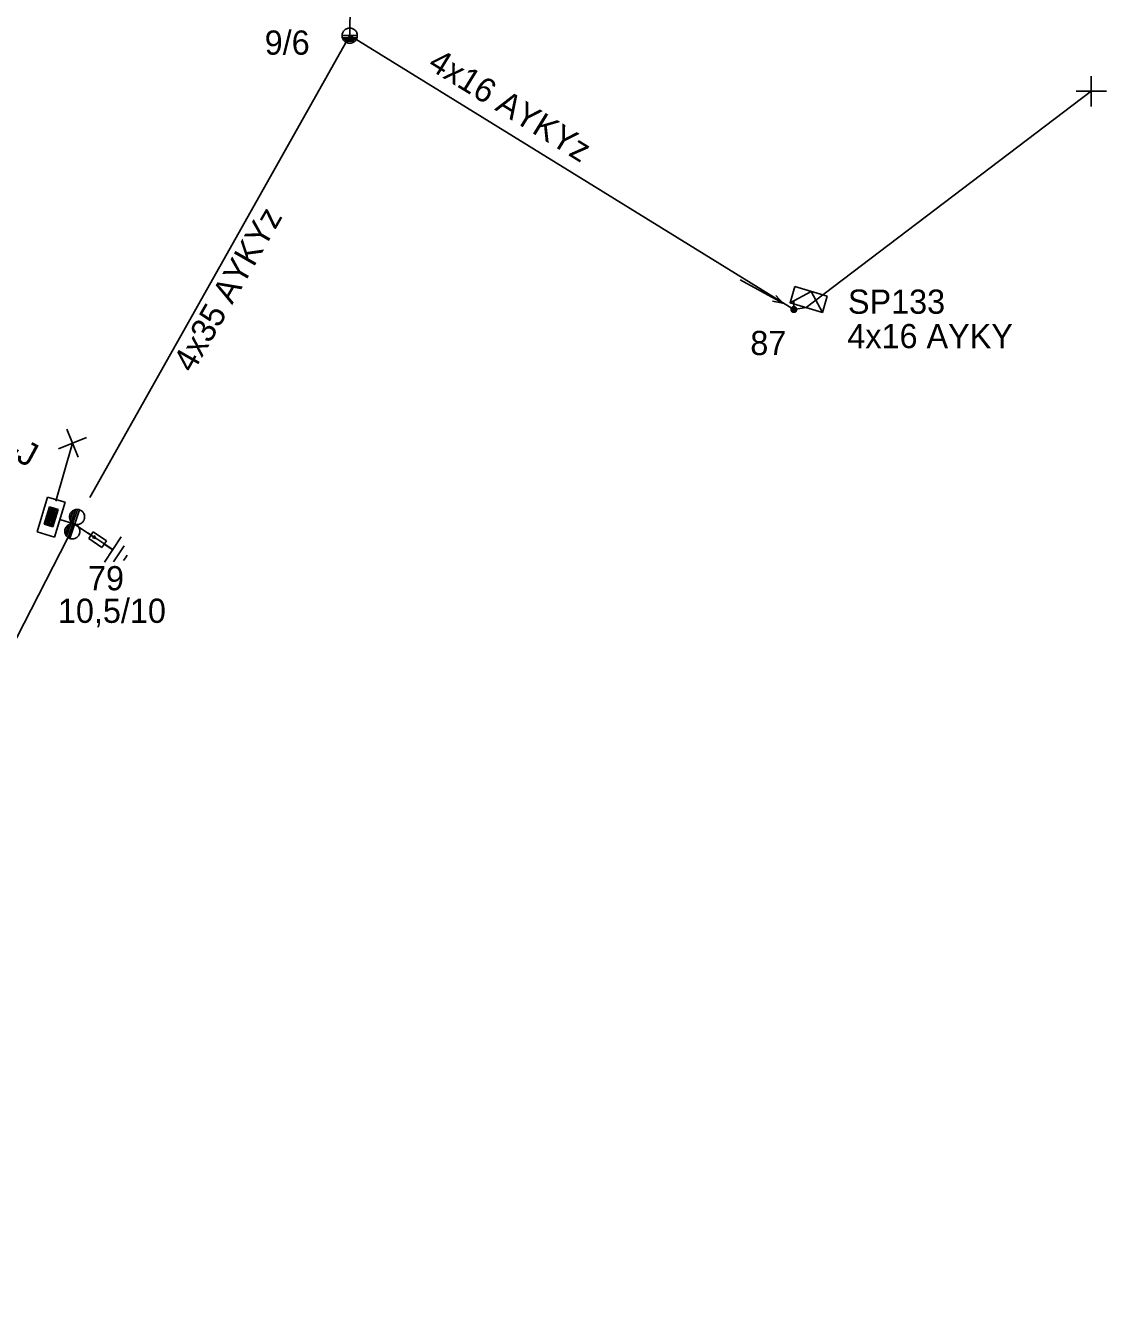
# Model space of a CAD drawing. Extents: x -788458 to -786145, y -1154772 to -1152372.
# Drawn here: x -787177.6 to -787132.9, y -1152514.5 to -1152461.7 of the extents above; entities that cross this region are included whole.
import ezdxf

# ---------------------------------------------------------------- set-up
doc = ezdxf.new("R2010")
doc.units = 0
for name, color, linetype in [('Vrstva 1', 7, 'Continuous'), ('Vrstva 12', 7, 'Continuous'), ('Vrstva 13', 7, 'Continuous'), ('Vrstva 14', 7, 'Continuous'), ('Vrstva 15', 7, 'Continuous'), ('Vrstva 16', 7, 'Continuous'), ('Vrstva 2', 7, 'Continuous'), ('Vrstva 28', 7, 'Continuous'), ('Vrstva 31', 7, 'Continuous'), ('Vrstva 33', 7, 'Continuous'), ('Vrstva 34', 7, 'Continuous'), ('Vrstva 5', 7, 'Continuous'), ('Vrstva 52', 7, 'Continuous'), ('Vrstva 53', 7, 'Continuous'), ('Vrstva 54', 7, 'Continuous'), ('Vrstva 59', 7, 'Continuous'), ('Vrstva 6', 7, 'Continuous'), ('Vrstva 8', 7, 'Continuous'), ('Vrstva 9', 7, 'Continuous')]:
    doc.layers.add(name, color=color, linetype=linetype)

# ---------------------------------------------------------------- blocks, each defined once
blk = doc.blocks.new('NN440')
at = {"layer": 'Vrstva 2'}
for points in [[(0.63, 0), (0.63, 0.06), (0.62, 0.13), (0.6, 0.19), (0.58, 0.25), (0.55, 0.31), (0.51, 0.37), (0.47, 0.42), (0.42, 0.46), (0.37, 0.51), (0.32, 0.54), (0.26, 0.57), (0.2, 0.59), (0.13, 0.61), (0.07, 0.62), (0, 0.63), (-0.06, 0.62), (-0.13, 0.61), (-0.19, 0.59), (-0.26, 0.57), (-0.31, 0.54), (-0.37, 0.51), (-0.42, 0.46), (-0.47, 0.42), (-0.51, 0.37), (-0.54, 0.31), (-0.57, 0.25), (-0.6, 0.19), (-0.62, 0.13), (-0.63, 0.06), (-0.63, 0), (-0.63, -0.07), (-0.62, -0.14), (-0.6, -0.2), (-0.57, -0.26), (-0.54, -0.32), (-0.51, -0.37), (-0.47, -0.43), (-0.42, -0.47), (-0.37, -0.51), (-0.31, -0.55), (-0.26, -0.58), (-0.19, -0.6), (-0.13, -0.62), (-0.06, -0.63), (0, -0.63), (0.07, -0.63), (0.13, -0.62), (0.2, -0.6), (0.26, -0.58), (0.32, -0.55), (0.37, -0.51), (0.42, -0.47), (0.47, -0.43), (0.51, -0.37), (0.55, -0.32), (0.58, -0.26), (0.6, -0.2), (0.62, -0.14), (0.63, -0.07), (0.63, 0)], [(-0.63, 0), (0.63, 0)], [(-0.6, -0.18), (0.57, -0.18)], [(-0.51, -0.32), (0.5, -0.32)], [(-0.37, -0.47), (0.35, -0.47)]]:
    blk.add_lwpolyline(points, dxfattribs=at)
blk = doc.blocks.new('NN450')
at = {"layer": 'Vrstva 2'}
for points in [[(0, 0), (0, 0.07), (-0.01, 0.13), (-0.03, 0.19), (-0.05, 0.25), (-0.08, 0.31), (-0.12, 0.37), (-0.16, 0.42), (-0.21, 0.46), (-0.26, 0.51), (-0.31, 0.54), (-0.37, 0.57), (-0.43, 0.59), (-0.5, 0.61), (-0.56, 0.62), (-0.63, 0.62), (-0.69, 0.62), (-0.75, 0.61), (-0.82, 0.59), (-0.88, 0.57), (-0.94, 0.54), (-0.99, 0.51), (-1.04, 0.46), (-1.09, 0.42), (-1.13, 0.37), (-1.17, 0.31), (-1.2, 0.25), (-1.22, 0.19), (-1.24, 0.13), (-1.25, 0.07), (-1.25, 0), (-1.25, -0.07), (-1.24, -0.13), (-1.22, -0.19), (-1.2, -0.25), (-1.17, -0.31), (-1.13, -0.37), (-1.09, -0.42), (-1.04, -0.46), (-0.99, -0.51), (-0.94, -0.54), (-0.88, -0.57), (-0.82, -0.59), (-0.75, -0.61), (-0.69, -0.62), (-0.62, -0.63), (-0.56, -0.62), (-0.5, -0.61), (-0.43, -0.59), (-0.37, -0.57), (-0.31, -0.54), (-0.26, -0.51), (-0.21, -0.46), (-0.16, -0.42), (-0.12, -0.37), (-0.08, -0.31), (-0.05, -0.25), (-0.03, -0.19), (-0.01, -0.13), (0, -0.07), (0, 0)], [(1.25, 0), (1.25, 0.07), (1.24, 0.13), (1.22, 0.19), (1.2, 0.25), (1.17, 0.31), (1.13, 0.37), (1.09, 0.42), (1.04, 0.46), (0.99, 0.51), (0.94, 0.54), (0.88, 0.57), (0.82, 0.59), (0.75, 0.61), (0.69, 0.62), (0.62, 0.62), (0.56, 0.62), (0.5, 0.61), (0.43, 0.59), (0.37, 0.57), (0.31, 0.54), (0.26, 0.51), (0.21, 0.46), (0.16, 0.42), (0.12, 0.37), (0.08, 0.31), (0.05, 0.25), (0.03, 0.19), (0.01, 0.13), (0, 0.07), (0, 0), (0, -0.07), (0.01, -0.13), (0.03, -0.19), (0.05, -0.25), (0.08, -0.31), (0.12, -0.37), (0.16, -0.42), (0.21, -0.46), (0.26, -0.51), (0.31, -0.54), (0.37, -0.57), (0.43, -0.59), (0.5, -0.61), (0.56, -0.62), (0.63, -0.63), (0.69, -0.62), (0.75, -0.61), (0.82, -0.59), (0.88, -0.57), (0.94, -0.54), (0.99, -0.51), (1.04, -0.46), (1.09, -0.42), (1.13, -0.37), (1.17, -0.31), (1.2, -0.25), (1.22, -0.19), (1.24, -0.13), (1.25, -0.07), (1.25, 0)], [(-1.25, 0), (1.25, 0)], [(-1.23, -0.16), (-0.02, -0.16)], [(-1.16, -0.32), (-0.09, -0.32)], [(-1.03, -0.47), (-0.22, -0.47)], [(0.02, -0.16), (1.23, -0.16)], [(0.09, -0.32), (1.16, -0.32)], [(0.22, -0.47), (1.03, -0.47)]]:
    blk.add_lwpolyline(points, dxfattribs=at)
blk = doc.blocks.new('NN565')
at = {"layer": 'Vrstva 2'}
for points in [[(0.015, 0.528), (0.015, 2.528)], [(0.157, 0.937), (0.015, 0.528), (-0.119, 0.937)]]:
    blk.add_lwpolyline(points, dxfattribs=at)
blk = doc.blocks.new('NN800')
at = {"layer": 'Vrstva 1'}
for points in [[(-0.442, 0.442), (0.442, -0.442)], [(-0.442, -0.442), (0.442, 0.442)]]:
    blk.add_lwpolyline(points, dxfattribs=at)
blk = doc.blocks.new('NN820')
at = {"layer": 'Vrstva 13'}
for points in [[(-0.003, 0.004), (-0.003, -1.049)], [(-0.165, -0.813), (0.165, -0.813)], [(-0.165, -1.473), (-0.165, -0.813)], [(-0.003, -1.049), (-0.062, -0.926)], [(-0.003, -1.049), (0.057, -0.926)], [(0.165, -0.813), (0.165, -1.473)], [(0.165, -1.473), (-0.165, -1.473)], [(-0.003, -1.473), (-0.003, -1.871)]]:
    blk.add_lwpolyline(points, dxfattribs=at)
blk = doc.blocks.new('NN620')
at = {"layer": 'Vrstva 8'}
for points in [[(0.752, 0.004), (-0.748, 0.004)], [(-0.748, 0.004), (-0.748, -0.746)], [(0.752, -0.746), (0.752, 0.004)], [(0.368, -0.18), (-0.376, -0.18)], [(-0.376, -0.18), (-0.376, -0.558)], [(0.321, -0.227), (-0.329, -0.227)], [(-0.329, -0.227), (-0.329, -0.51)], [(-0.329, -0.51), (0.321, -0.51)], [(0.274, -0.274), (-0.281, -0.274)], [(-0.281, -0.274), (-0.281, -0.463)], [(-0.281, -0.463), (0.274, -0.463)], [(0.227, -0.321), (-0.234, -0.321)], [(-0.234, -0.321), (-0.234, -0.416)], [(-0.234, -0.416), (0.227, -0.416)], [(-0.193, -0.369), (0.185, -0.369)], [(0.227, -0.416), (0.227, -0.321)], [(0.274, -0.463), (0.274, -0.274)], [(0.321, -0.51), (0.321, -0.227)], [(0.368, -0.558), (0.368, -0.18)], [(-0.748, -0.746), (0.752, -0.746)], [(-0.376, -0.558), (0.368, -0.558)]]:
    blk.add_lwpolyline(points, dxfattribs=at)
blk = doc.blocks.new('NN630')
at = {"layer": 'Vrstva 9'}
for points in [[(-0.003, -0.7), (-0.703, 0)], [(-0.703, -0.7), (-0.703, 0), (0.697, 0), (0.697, -0.7)], [(-0.003, -0.7), (0.697, 0)], [(-0.703, -0.7), (0.697, -0.7)]]:
    blk.add_lwpolyline(points, dxfattribs=at)
blk = doc.blocks.new('NN810')
at = {"layer": 'Vrstva 14'}
for points in [[(0.004, -0.64), (0.004, -1.89)], [(0.629, -1.89), (-0.621, -1.89)], [(0.388, -2.2), (-0.399, -2.2)], [(0.004, -2.515), (-0.124, -2.515)], [(0.137, -2.515), (0.004, -2.515)]]:
    blk.add_lwpolyline(points, dxfattribs=at)
blk = doc.blocks.new('NN500')
at = {"layer": 'Vrstva 2'}
for points in [[(0, -0.24), (0.02, -0.23), (0.05, -0.23), (0.07, -0.22), (0.09, -0.22), (0.12, -0.2), (0.14, -0.19), (0.16, -0.18), (0.17, -0.16), (0.19, -0.14), (0.2, -0.12), (0.21, -0.1), (0.22, -0.07), (0.23, -0.05), (0.23, -0.02), (0.23, 0), (0.23, 0.02), (0.23, 0.05), (0.22, 0.07), (0.21, 0.1), (0.2, 0.12), (0.19, 0.14), (0.17, 0.16), (0.16, 0.17), (0.14, 0.19), (0.12, 0.2), (0.09, 0.21), (0.07, 0.22), (0.05, 0.23), (0.02, 0.23), (0, 0.23), (-0.03, 0.23), (-0.05, 0.23), (-0.07, 0.22), (-0.1, 0.21), (-0.12, 0.2), (-0.14, 0.19), (-0.16, 0.17), (-0.18, 0.16), (-0.19, 0.14), (-0.2, 0.12), (-0.22, 0.1), (-0.22, 0.07), (-0.23, 0.05), (-0.23, 0.02), (-0.24, 0), (-0.23, -0.02), (-0.23, -0.05), (-0.22, -0.07), (-0.22, -0.1), (-0.2, -0.12), (-0.19, -0.14), (-0.18, -0.16), (-0.16, -0.18), (-0.14, -0.19), (-0.12, -0.2), (-0.1, -0.22), (-0.07, -0.22), (-0.05, -0.23), (-0.03, -0.23), (0, -0.24)], [(0, -0.24), (0.02, -0.23), (0.05, -0.23), (0.07, -0.22), (0.09, -0.22), (0.12, -0.2), (0.14, -0.19), (0.16, -0.18), (0.17, -0.16), (0.19, -0.14), (0.2, -0.12), (0.21, -0.1), (0.22, -0.07), (0.23, -0.05), (0.23, -0.02), (0.23, 0), (0.23, 0.02), (0.23, 0.05), (0.22, 0.07), (0.21, 0.1), (0.2, 0.12), (0.19, 0.14), (0.17, 0.16), (0.16, 0.17), (0.14, 0.19), (0.12, 0.2), (0.09, 0.21), (0.07, 0.22), (0.05, 0.23), (0.02, 0.23), (0, 0.23), (-0.03, 0.23), (-0.05, 0.23), (-0.07, 0.22), (-0.1, 0.21), (-0.12, 0.2), (-0.14, 0.19), (-0.16, 0.17), (-0.18, 0.16), (-0.19, 0.14), (-0.2, 0.12), (-0.22, 0.1), (-0.22, 0.07), (-0.23, 0.05), (-0.23, 0.02), (-0.24, 0), (-0.23, -0.02), (-0.23, -0.05), (-0.22, -0.07), (-0.22, -0.1), (-0.2, -0.12), (-0.19, -0.14), (-0.18, -0.16), (-0.16, -0.18), (-0.14, -0.19), (-0.12, -0.2), (-0.1, -0.22), (-0.07, -0.22), (-0.05, -0.23), (-0.03, -0.23), (0, -0.24)], [(0, -0.21), (0.02, -0.2), (0.04, -0.2), (0.06, -0.2), (0.08, -0.19), (0.1, -0.18), (0.12, -0.17), (0.14, -0.15), (0.15, -0.14), (0.16, -0.12), (0.18, -0.1), (0.19, -0.08), (0.19, -0.06), (0.2, -0.04), (0.2, -0.02), (0.2, 0), (0.2, 0.02), (0.2, 0.04), (0.19, 0.06), (0.19, 0.08), (0.18, 0.1), (0.16, 0.12), (0.15, 0.14), (0.14, 0.15), (0.12, 0.17), (0.1, 0.18), (0.08, 0.19), (0.06, 0.19), (0.04, 0.2), (0.02, 0.2), (0, 0.2), (-0.02, 0.2), (-0.04, 0.2), (-0.06, 0.19), (-0.08, 0.19), (-0.1, 0.18), (-0.12, 0.17), (-0.14, 0.15), (-0.15, 0.14), (-0.17, 0.12), (-0.18, 0.1), (-0.19, 0.08), (-0.2, 0.06), (-0.2, 0.04), (-0.21, 0.02), (-0.21, 0), (-0.21, -0.02), (-0.2, -0.04), (-0.2, -0.06), (-0.19, -0.08), (-0.18, -0.1), (-0.17, -0.12), (-0.15, -0.14), (-0.14, -0.15), (-0.12, -0.17), (-0.1, -0.18), (-0.08, -0.19), (-0.06, -0.2), (-0.04, -0.2), (-0.02, -0.2), (0, -0.21)], [(0, -0.18), (0.02, -0.18), (0.04, -0.17), (0.05, -0.17), (0.07, -0.16), (0.09, -0.15), (0.1, -0.14), (0.12, -0.13), (0.13, -0.12), (0.14, -0.1), (0.15, -0.09), (0.16, -0.07), (0.17, -0.05), (0.17, -0.04), (0.17, -0.02), (0.17, 0), (0.17, 0.02), (0.17, 0.04), (0.17, 0.05), (0.16, 0.07), (0.15, 0.09), (0.14, 0.1), (0.13, 0.12), (0.12, 0.13), (0.1, 0.14), (0.09, 0.15), (0.07, 0.16), (0.05, 0.17), (0.04, 0.17), (0.02, 0.17), (0, 0.18), (-0.02, 0.17), (-0.04, 0.17), (-0.06, 0.17), (-0.07, 0.16), (-0.09, 0.15), (-0.1, 0.14), (-0.12, 0.13), (-0.13, 0.12), (-0.14, 0.1), (-0.15, 0.09), (-0.16, 0.07), (-0.17, 0.05), (-0.17, 0.04), (-0.18, 0.02), (-0.18, 0), (-0.18, -0.02), (-0.17, -0.04), (-0.17, -0.05), (-0.16, -0.07), (-0.15, -0.09), (-0.14, -0.1), (-0.13, -0.12), (-0.12, -0.13), (-0.1, -0.14), (-0.09, -0.15), (-0.07, -0.16), (-0.06, -0.17), (-0.04, -0.17), (-0.02, -0.18), (0, -0.18)], [(0, -0.15), (0.01, -0.15), (0.03, -0.14), (0.04, -0.14), (0.06, -0.13), (0.07, -0.13), (0.08, -0.12), (0.1, -0.11), (0.11, -0.1), (0.12, -0.09), (0.13, -0.07), (0.13, -0.06), (0.14, -0.05), (0.14, -0.03), (0.14, -0.02), (0.14, 0), (0.14, 0.01), (0.14, 0.03), (0.14, 0.04), (0.13, 0.06), (0.13, 0.07), (0.12, 0.09), (0.11, 0.1), (0.1, 0.11), (0.08, 0.12), (0.07, 0.13), (0.06, 0.13), (0.04, 0.14), (0.03, 0.14), (0.01, 0.14), (0, 0.15), (-0.02, 0.14), (-0.03, 0.14), (-0.05, 0.14), (-0.06, 0.13), (-0.07, 0.13), (-0.09, 0.12), (-0.1, 0.11), (-0.11, 0.1), (-0.12, 0.09), (-0.13, 0.07), (-0.13, 0.06), (-0.14, 0.04), (-0.14, 0.03), (-0.15, 0.01), (-0.15, 0), (-0.15, -0.02), (-0.14, -0.03), (-0.14, -0.05), (-0.13, -0.06), (-0.13, -0.07), (-0.12, -0.09), (-0.11, -0.1), (-0.1, -0.11), (-0.09, -0.12), (-0.07, -0.13), (-0.06, -0.13), (-0.05, -0.14), (-0.03, -0.14), (-0.02, -0.15), (0, -0.15)], [(0, -0.12), (0.01, -0.12), (0.02, -0.11), (0.03, -0.11), (0.05, -0.11), (0.06, -0.1), (0.07, -0.09), (0.08, -0.09), (0.09, -0.08), (0.09, -0.07), (0.1, -0.06), (0.11, -0.05), (0.11, -0.04), (0.11, -0.02), (0.11, -0.01), (0.12, 0), (0.11, 0.01), (0.11, 0.02), (0.11, 0.04), (0.11, 0.05), (0.1, 0.06), (0.09, 0.07), (0.09, 0.08), (0.08, 0.09), (0.07, 0.09), (0.06, 0.1), (0.05, 0.11), (0.03, 0.11), (0.02, 0.11), (0.01, 0.12), (0, 0.12), (-0.01, 0.12), (-0.03, 0.11), (-0.04, 0.11), (-0.05, 0.11), (-0.06, 0.1), (-0.07, 0.09), (-0.08, 0.09), (-0.09, 0.08), (-0.1, 0.07), (-0.1, 0.06), (-0.11, 0.05), (-0.11, 0.04), (-0.12, 0.02), (-0.12, 0.01), (-0.12, 0), (-0.12, -0.01), (-0.12, -0.02), (-0.11, -0.04), (-0.11, -0.05), (-0.1, -0.06), (-0.1, -0.07), (-0.09, -0.08), (-0.08, -0.09), (-0.07, -0.09), (-0.06, -0.1), (-0.05, -0.11), (-0.04, -0.11), (-0.03, -0.11), (-0.01, -0.12), (0, -0.12)], [(0, -0.09), (0.01, -0.09), (0.02, -0.09), (0.03, -0.08), (0.03, -0.08), (0.04, -0.08), (0.05, -0.07), (0.06, -0.07), (0.06, -0.06), (0.07, -0.05), (0.07, -0.04), (0.08, -0.04), (0.08, -0.03), (0.08, -0.02), (0.09, -0.01), (0.09, 0), (0.09, 0.01), (0.08, 0.02), (0.08, 0.03), (0.08, 0.03), (0.07, 0.04), (0.07, 0.05), (0.06, 0.06), (0.06, 0.06), (0.05, 0.07), (0.04, 0.07), (0.03, 0.08), (0.03, 0.08), (0.02, 0.08), (0.01, 0.09), (0, 0.09), (-0.01, 0.09), (-0.02, 0.08), (-0.03, 0.08), (-0.04, 0.08), (-0.04, 0.07), (-0.05, 0.07), (-0.06, 0.06), (-0.07, 0.06), (-0.07, 0.05), (-0.08, 0.04), (-0.08, 0.03), (-0.08, 0.03), (-0.09, 0.02), (-0.09, 0.01), (-0.09, 0), (-0.09, -0.01), (-0.09, -0.02), (-0.08, -0.03), (-0.08, -0.04), (-0.08, -0.04), (-0.07, -0.05), (-0.07, -0.06), (-0.06, -0.07), (-0.05, -0.07), (-0.04, -0.08), (-0.04, -0.08), (-0.03, -0.08), (-0.02, -0.09), (-0.01, -0.09), (0, -0.09)], [(0, -0.06), (0, -0.06), (0.01, -0.06), (0.02, -0.05), (0.02, -0.05), (0.03, -0.05), (0.03, -0.05), (0.04, -0.04), (0.04, -0.04), (0.05, -0.03), (0.05, -0.03), (0.05, -0.02), (0.05, -0.02), (0.05, -0.01), (0.06, -0.01), (0.06, 0), (0.06, 0.01), (0.05, 0.01), (0.05, 0.02), (0.05, 0.02), (0.05, 0.03), (0.05, 0.03), (0.04, 0.04), (0.04, 0.04), (0.03, 0.05), (0.03, 0.05), (0.02, 0.05), (0.02, 0.05), (0.01, 0.06), (0, 0.06), (0, 0.06), (-0.01, 0.06), (-0.01, 0.06), (-0.02, 0.05), (-0.02, 0.05), (-0.03, 0.05), (-0.03, 0.05), (-0.04, 0.04), (-0.04, 0.04), (-0.05, 0.03), (-0.05, 0.03), (-0.05, 0.02), (-0.06, 0.02), (-0.06, 0.01), (-0.06, 0.01), (-0.06, 0), (-0.06, -0.01), (-0.06, -0.01), (-0.06, -0.02), (-0.05, -0.02), (-0.05, -0.03), (-0.05, -0.03), (-0.04, -0.04), (-0.04, -0.04), (-0.03, -0.05), (-0.03, -0.05), (-0.02, -0.05), (-0.02, -0.05), (-0.01, -0.06), (-0.01, -0.06), (0, -0.06)], [(0, -0.03), (0, -0.03), (0, -0.03), (0.01, -0.03), (0.01, -0.03), (0.01, -0.02), (0.02, -0.02), (0.02, -0.02), (0.02, -0.02), (0.02, -0.02), (0.02, -0.01), (0.02, -0.01), (0.03, -0.01), (0.03, -0.01), (0.03, 0), (0.03, 0), (0.03, 0), (0.03, 0.01), (0.03, 0.01), (0.02, 0.01), (0.02, 0.01), (0.02, 0.02), (0.02, 0.02), (0.02, 0.02), (0.02, 0.02), (0.01, 0.02), (0.01, 0.02), (0.01, 0.03), (0, 0.03), (0, 0.03), (0, 0.03), (0, 0.03), (-0.01, 0.03), (-0.01, 0.03), (-0.01, 0.02), (-0.02, 0.02), (-0.02, 0.02), (-0.02, 0.02), (-0.02, 0.02), (-0.02, 0.02), (-0.03, 0.01), (-0.03, 0.01), (-0.03, 0.01), (-0.03, 0.01), (-0.03, 0), (-0.03, 0), (-0.03, 0), (-0.03, -0.01), (-0.03, -0.01), (-0.03, -0.01), (-0.03, -0.01), (-0.02, -0.02), (-0.02, -0.02), (-0.02, -0.02), (-0.02, -0.02), (-0.02, -0.02), (-0.01, -0.03), (-0.01, -0.03), (-0.01, -0.03), (0, -0.03), (0, -0.03)], [(0.23, 0), (0.7, 0)]]:
    blk.add_lwpolyline(points, dxfattribs=at)

msp = doc.modelspace()

# ---------------------------------------------------------------- linework, layer by layer
at = {"layer": 'Vrstva 1'}
msp.add_lwpolyline([(-787175.56, -1152482.27), (-787192.07, -1152514.518)], dxfattribs=at)
at = {"layer": 'Vrstva 5'}
msp.add_lwpolyline([(-787175.56, -1152482.27), (-787176.182, -1152482.082)], dxfattribs=at)
at = {"layer": 'Vrstva 52'}
for points in [[(-787164.2, -1152462.08), (-787164.02, -1152444.92), (-787151.88, -1152428.69), (-787163.61, -1152405.19), (-787176.59, -1152379.26)], [(-787174.941, -1152481.17), (-787164.2, -1152462.08)], [(-787164.2, -1152462.08), (-787145.85, -1152473.4)], [(-787145.85, -1152473.4), (-787145.34, -1152473.32)]]:
    msp.add_lwpolyline(points, dxfattribs=at)
at = {"layer": 'Vrstva 59'}
for points in [[(-787145.34, -1152473.32), (-787133.56, -1152464.38)], [(-787176.345, -1152481.324), (-787175.65, -1152478.921)]]:
    msp.add_lwpolyline(points, dxfattribs=at)

# ---------------------------------------------------------------- block references
at = {"layer": 'Vrstva 13', "xscale": 0.5, "yscale": 0.5}
msp.add_blockref('NN440', (-787164.2, -1152462.08), dxfattribs=at)
at = {"layer": 'Vrstva 13', "rotation": 61.4167166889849}
msp.add_blockref('NN565', (-787145.85, -1152473.4), dxfattribs=at)
at = {"layer": 'Vrstva 13'}
for name, p, xscale, yscale, rotation in [('NN500', (-787145.85, -1152473.4), 0.5, 0.5, 90), ('NN450', (-787175.56, -1152482.27), 0.49999999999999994, 0.5000000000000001, -108.35549412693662)]:
    msp.add_blockref(name, p, dxfattribs=dict(at, xscale=xscale, yscale=yscale, rotation=rotation))
at = {"layer": 'Vrstva 15', "rotation": 56.18411342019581}
msp.add_blockref('NN810', (-787175.56, -1152482.27), dxfattribs=at)
at = {"layer": 'Vrstva 16', "rotation": 55.80348958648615}
msp.add_blockref('NN820', (-787175.56, -1152482.27), dxfattribs=at)
at = {"layer": 'Vrstva 28', "rotation": -106.79837172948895}
msp.add_blockref('NN620', (-787176.182, -1152482.082), dxfattribs=at)
at = {"layer": 'Vrstva 31', "rotation": 163.42599228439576}
msp.add_blockref('NN630', (-787145.34, -1152473.32), dxfattribs=at)
at = {"layer": 'Vrstva 34'}
for p, rotation in [((-787133.56, -1152464.38), 45), ((-787175.65, -1152478.921), -112.65523273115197)]:
    msp.add_blockref('NN800', p, dxfattribs=dict(at, rotation=rotation))

# ---------------------------------------------------------------- texts
at = {"layer": 'Vrstva 12'}
for s, p in [('9/6', (-787167.712, -1152462.868)), ('10,5/10', (-787176.255, -1152486.35))]:
    msp.add_text(s, height=1, dxfattribs=at).set_placement(p)
at = {"layer": 'Vrstva 14'}
for s, p in [('87', (-787147.648, -1152475.282)), ('79', (-787175.013, -1152485.005))]:
    msp.add_text(s, height=1, dxfattribs=at).set_placement(p)
at = {"layer": 'Vrstva 33'}
msp.add_text('SP133', height=1, dxfattribs=at).set_placement((-787143.614, -1152473.575))
at = {"layer": 'Vrstva 53'}
for s, rotation, p in [('4x16 AYKYz', 328.33, (-787161.024, -1152463.414)), ('4x35 AYKYz', 60.195, (-787170.683, -1152476.063))]:
    msp.add_text(s, height=1, rotation=rotation, dxfattribs=at).set_placement(p)
at = {"layer": 'Vrstva 54'}
msp.add_text('4x16 AYKY', height=1, dxfattribs=at).set_placement((-787143.639, -1152474.998))
at = {"layer": 'Vrstva 6'}
msp.add_text('4x95 1-NAYY-J', height=1, rotation=331.708, dxfattribs=at).set_placement((-787185.548, -1152475.583))

doc.saveas('drawing.dxf')
